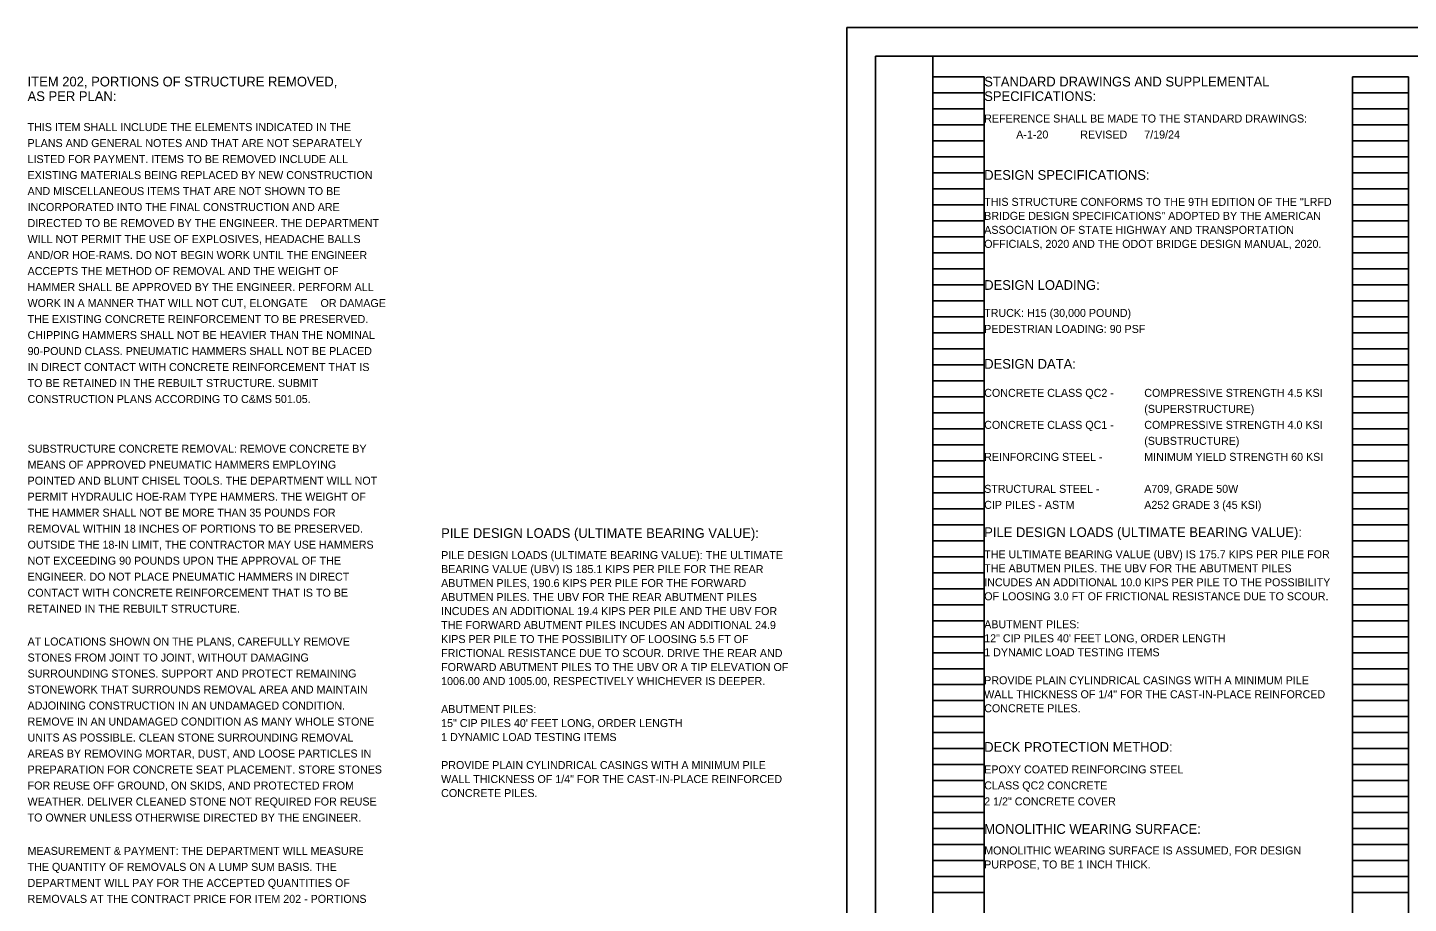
# Model space of a CAD drawing. Extents: x -14.3 to 34, y -8.8 to 27.3.
# Drawn here: x -14.33 to 9.82, y 6.67 to 22 of the extents above; entities that cross this region are included whole.
import ezdxf

# ---------------------------------------------------------------- set-up
doc = ezdxf.new("R2010")
doc.units = 0
for name, color, linetype in [('BR_P_Gen_Text', 7, 'Continuous'), ('SH_Border', 7, 'Continuous'), ('SH_Cut_Line', 7, 'Continuous'), ('SH_Data', 7, 'Continuous')]:
    doc.layers.add(name, color=color, linetype=linetype)

msp = doc.modelspace()

# ---------------------------------------------------------------- linework, layer by layer
at = {"layer": 'SH_Border'}
for points in [[(0.5, 21.5), (1.5, 21.5), (1.5, 0.5), (0.5, 0.5)], [(1.5, 21.5), (33.5, 21.5), (33.5, 0.5), (1.5, 0.5)]]:
    msp.add_lwpolyline(points, close=True, dxfattribs=at)
at = {"layer": 'SH_Cut_Line'}
msp.add_lwpolyline([(0, 0), (34, 0), (34, 22), (0, 22)], close=True, dxfattribs=at)
at = {"layer": 'SH_Data'}
for p, q in [((1.5, 0.98), (1.5, 21.14)), ((1.5, 21.14), (2.4, 21.14)), ((2.4, 0.98), (2.4, 21.14)), ((8.84, 0.98), (8.84, 21.14)), ((8.84, 21.14), (9.82, 21.14)), ((9.82, 0.98), (9.82, 21.14)), ((1.5, 20.86), (2.4, 20.86)), ((8.84, 20.86), (9.82, 20.86)), ((1.5, 20.58), (2.4, 20.58)), ((8.84, 20.58), (9.82, 20.58)), ((1.5, 20.3), (2.4, 20.3)), ((8.84, 20.3), (9.82, 20.3)), ((1.5, 20.02), (2.4, 20.02)), ((8.84, 20.02), (9.82, 20.02)), ((1.5, 19.74), (2.4, 19.74)), ((8.84, 19.74), (9.82, 19.74)), ((1.5, 19.46), (2.4, 19.46)), ((8.84, 19.46), (9.82, 19.46)), ((1.5, 19.18), (2.4, 19.18)), ((8.84, 19.18), (9.82, 19.18)), ((1.5, 18.9), (2.4, 18.9)), ((8.84, 18.9), (9.82, 18.9)), ((1.5, 18.62), (2.4, 18.62)), ((8.84, 18.62), (9.82, 18.62)), ((1.5, 18.34), (2.4, 18.34)), ((8.84, 18.34), (9.82, 18.34)), ((1.5, 18.06), (2.4, 18.06)), ((8.84, 18.06), (9.82, 18.06)), ((1.5, 17.78), (2.4, 17.78)), ((8.84, 17.78), (9.82, 17.78)), ((1.5, 17.5), (2.4, 17.5)), ((8.84, 17.5), (9.82, 17.5)), ((1.5, 17.22), (2.4, 17.22)), ((8.84, 17.22), (9.82, 17.22)), ((1.5, 16.94), (2.4, 16.94)), ((8.84, 16.94), (9.82, 16.94)), ((1.5, 16.66), (2.4, 16.66)), ((8.84, 16.66), (9.82, 16.66)), ((1.5, 16.38), (2.4, 16.38)), ((8.84, 16.38), (9.82, 16.38)), ((1.5, 16.1), (2.4, 16.1)), ((8.84, 16.1), (9.82, 16.1)), ((1.5, 15.82), (2.4, 15.82)), ((8.84, 15.82), (9.82, 15.82)), ((1.5, 15.54), (2.4, 15.54)), ((8.84, 15.54), (9.82, 15.54)), ((1.5, 15.26), (2.4, 15.26)), ((8.84, 15.26), (9.82, 15.26)), ((1.5, 14.98), (2.4, 14.98)), ((8.84, 14.98), (9.82, 14.98)), ((1.5, 14.7), (2.4, 14.7)), ((8.84, 14.7), (9.82, 14.7)), ((1.5, 14.42), (2.4, 14.42)), ((8.84, 14.42), (9.82, 14.42)), ((1.5, 14.14), (2.4, 14.14)), ((8.84, 14.14), (9.82, 14.14)), ((1.5, 13.86), (2.4, 13.86)), ((8.84, 13.86), (9.82, 13.86)), ((1.5, 13.58), (2.4, 13.58)), ((8.84, 13.58), (9.82, 13.58)), ((1.5, 13.3), (2.4, 13.3)), ((8.84, 13.3), (9.82, 13.3)), ((1.5, 13.02), (2.4, 13.02)), ((8.84, 13.02), (9.82, 13.02)), ((1.5, 12.74), (2.4, 12.74)), ((8.84, 12.74), (9.82, 12.74)), ((1.5, 12.46), (2.4, 12.46)), ((8.84, 12.46), (9.82, 12.46)), ((1.5, 12.18), (2.4, 12.18)), ((8.84, 12.18), (9.82, 12.18)), ((1.5, 11.9), (2.4, 11.9)), ((8.84, 11.9), (9.82, 11.9)), ((1.5, 11.62), (2.4, 11.62)), ((8.84, 11.62), (9.82, 11.62)), ((1.5, 11.34), (2.4, 11.34)), ((8.84, 11.34), (9.82, 11.34)), ((1.5, 11.06), (2.4, 11.06)), ((8.84, 11.06), (9.82, 11.06)), ((1.5, 10.78), (2.4, 10.78)), ((8.84, 10.78), (9.82, 10.78)), ((1.5, 10.5), (2.4, 10.5)), ((8.84, 10.5), (9.82, 10.5)), ((1.5, 10.22), (2.4, 10.22)), ((8.84, 10.22), (9.82, 10.22)), ((1.5, 9.94), (2.4, 9.94)), ((8.84, 9.94), (9.82, 9.94)), ((1.5, 9.66), (2.4, 9.66)), ((8.84, 9.66), (9.82, 9.66)), ((1.5, 9.38), (2.4, 9.38)), ((8.84, 9.38), (9.82, 9.38)), ((1.5, 9.1), (2.4, 9.1)), ((8.84, 9.1), (9.82, 9.1)), ((1.5, 8.82), (2.4, 8.82)), ((8.84, 8.82), (9.82, 8.82)), ((1.5, 8.54), (2.4, 8.54)), ((8.84, 8.54), (9.82, 8.54)), ((1.5, 8.26), (2.4, 8.26)), ((8.84, 8.26), (9.82, 8.26)), ((1.5, 7.98), (2.4, 7.98)), ((8.84, 7.98), (9.82, 7.98)), ((1.5, 7.7), (2.4, 7.7)), ((8.84, 7.7), (9.82, 7.7)), ((1.5, 7.42), (2.4, 7.42)), ((8.84, 7.42), (9.82, 7.42)), ((1.5, 7.14), (2.4, 7.14)), ((8.84, 7.14), (9.82, 7.14)), ((1.5, 6.86), (2.4, 6.86)), ((8.84, 6.86), (9.82, 6.86))]:
    msp.add_line(p, q, dxfattribs=at)

# ---------------------------------------------------------------- texts
at = {"layer": 'BR_P_Gen_Text'}
for s, height, p in [('ITEM 202, PORTIONS OF STRUCTURE REMOVED, ', 0.17, (-14.334, 20.97)), ('STANDARD DRAWINGS AND SUPPLEMENTAL ', 0.17, (2.4, 20.97)), ('AS PER PLAN:', 0.17, (-14.334, 20.715)), ('SPECIFICATIONS:', 0.17, (2.4, 20.715)), ('THIS ITEM SHALL INCLUDE THE ELEMENTS INDICATED IN THE ', 0.14, (-14.334, 20.189)), ('REFERENCE SHALL BE MADE TO THE STANDARD DRAWINGS:', 0.14, (2.4, 20.339)), ('PLANS AND GENERAL NOTES AND THAT ARE NOT SEPARATELY ', 0.14, (-14.334, 19.909)), ('A-1-20', 0.14, (2.96, 20.059)), ('REVISED', 0.14, (4.08, 20.059)), ('7/19/24', 0.14, (5.2, 20.059)), ('LISTED FOR PAYMENT. ITEMS TO BE REMOVED INCLUDE ALL ', 0.14, (-14.334, 19.629)), ('EXISTING MATERIALS BEING REPLACED BY NEW CONSTRUCTION ', 0.14, (-14.334, 19.349)), ('DESIGN SPECIFICATIONS:', 0.17, (2.4, 19.336)), ('AND MISCELLANEOUS ITEMS THAT ARE NOT SHOWN TO BE ', 0.14, (-14.334, 19.069)), ('INCORPORATED INTO THE FINAL CONSTRUCTION AND ARE ', 0.14, (-14.334, 18.789)), ('THIS STRUCTURE CONFORMS TO THE 9TH EDITION OF THE "LRFD ', 0.14, (2.4, 18.88)), ('DIRECTED TO BE REMOVED BY THE ENGINEER. THE DEPARTMENT ', 0.14, (-14.334, 18.509)), ('BRIDGE DESIGN SPECIFICATIONS" ADOPTED BY THE AMERICAN ', 0.14, (2.4, 18.635)), ('WILL NOT PERMIT THE USE OF EXPLOSIVES, HEADACHE BALLS ', 0.14, (-14.334, 18.229)), ('ASSOCIATION OF STATE HIGHWAY AND TRANSPORTATION ', 0.14, (2.4, 18.39)), ('OFFICIALS, 2020 AND THE ODOT BRIDGE DESIGN MANUAL, 2020.', 0.14, (2.4, 18.145)), ('AND/OR HOE-RAMS. DO NOT BEGIN WORK UNTIL THE ENGINEER ', 0.14, (-14.334, 17.949)), ('ACCEPTS THE METHOD OF REMOVAL AND THE WEIGHT OF ', 0.14, (-14.334, 17.669)), ('HAMMER SHALL BE APPROVED BY THE ENGINEER. PERFORM ALL ', 0.14, (-14.334, 17.389)), ('DESIGN LOADING:', 0.17, (2.4, 17.41)), ('WORK IN A MANNER THAT WILL NOT CUT, ELONGATE', 0.14, (-14.334, 17.109)), (' OR DAMAGE ', 0.14, (-9.262, 17.109)), ('THE EXISTING CONCRETE REINFORCEMENT TO BE PRESERVED. ', 0.14, (-14.334, 16.829)), ('TRUCK: H15 (30,000 POUND)', 0.14, (2.4, 16.936)), ('CHIPPING HAMMERS SHALL NOT BE HEAVIER THAN THE NOMINAL ', 0.14, (-14.334, 16.549)), ('PEDESTRIAN LOADING: 90 PSF', 0.14, (2.4, 16.656)), ('90-POUND CLASS. PNEUMATIC HAMMERS SHALL NOT BE PLACED ', 0.14, (-14.334, 16.269)), ('DESIGN DATA:', 0.17, (2.4, 16.03)), ('IN DIRECT CONTACT WITH CONCRETE REINFORCEMENT THAT IS ', 0.14, (-14.334, 15.989)), ('TO BE RETAINED IN THE REBUILT STRUCTURE. SUBMIT ', 0.14, (-14.334, 15.709)), ('CONSTRUCTION PLANS ACCORDING TO C&MS 501.05. ', 0.14, (-14.334, 15.429)), ('CONCRETE CLASS QC2 - ', 0.14, (2.4, 15.537)), ('COMPRESSIVE STRENGTH 4.5 KSI ', 0.14, (5.2, 15.537)), ('(SUPERSTRUCTURE)', 0.14, (5.2, 15.257)), ('CONCRETE CLASS QC1 - ', 0.14, (2.4, 14.977)), ('COMPRESSIVE STRENGTH 4.0 KSI ', 0.14, (5.2, 14.977)), ('(SUBSTRUCTURE)', 0.14, (5.2, 14.697)), ('SUBSTRUCTURE CONCRETE REMOVAL: REMOVE CONCRETE BY ', 0.14, (-14.334, 14.56)), ('REINFORCING STEEL - ', 0.14, (2.4, 14.417)), ('MINIMUM YIELD STRENGTH 60 KSI', 0.14, (5.2, 14.417)), ('MEANS OF APPROVED PNEUMATIC HAMMERS EMPLOYING ', 0.14, (-14.334, 14.28)), ('POINTED AND BLUNT CHISEL TOOLS. THE DEPARTMENT WILL NOT ', 0.14, (-14.334, 14)), ('PERMIT HYDRAULIC HOE-RAM TYPE HAMMERS. THE WEIGHT OF ', 0.14, (-14.334, 13.72)), ('STRUCTURAL STEEL - ', 0.14, (2.4, 13.857)), ('A709, GRADE 50W ', 0.14, (5.2, 13.857)), ('THE HAMMER SHALL NOT BE MORE THAN 35 POUNDS FOR ', 0.14, (-14.334, 13.44)), ('CIP PILES - ASTM ', 0.14, (2.4, 13.577)), ('A252 GRADE 3 (45 KSI)', 0.14, (5.2, 13.577)), ('REMOVAL WITHIN 18 INCHES OF PORTIONS TO BE PRESERVED. ', 0.14, (-14.334, 13.16)), ('PILE DESIGN LOADS (ULTIMATE BEARING VALUE):', 0.17, (-7.1, 13.068)), ('PILE DESIGN LOADS (ULTIMATE BEARING VALUE):', 0.17, (2.4, 13.083)), ('OUTSIDE THE 18-IN LIMIT, THE CONTRACTOR MAY USE HAMMERS ', 0.14, (-14.334, 12.88)), ('PILE DESIGN LOADS (ULTIMATE BEARING VALUE): THE ULTIMATE ', 0.14, (-7.1, 12.698)), ('THE ULTIMATE BEARING VALUE (UBV) IS 175.7 KIPS PER PILE FOR ', 0.14, (2.4, 12.712)), ('NOT EXCEEDING 90 POUNDS UPON THE APPROVAL OF THE ', 0.14, (-14.334, 12.6)), ('BEARING VALUE (UBV) IS 185.1 KIPS PER PILE FOR THE REAR ', 0.14, (-7.1, 12.453)), ('THE ABUTMEN PILES. THE UBV FOR THE ABUTMENT PILES ', 0.14, (2.4, 12.467)), ('ENGINEER. DO NOT PLACE PNEUMATIC HAMMERS IN DIRECT ', 0.14, (-14.334, 12.32)), ('ABUTMEN PILES, 190.6 KIPS PER PILE FOR THE FORWARD ', 0.14, (-7.1, 12.208)), ('INCUDES AN ADDITIONAL 10.0 KIPS PER PILE TO THE POSSIBILITY ', 0.14, (2.4, 12.222)), ('CONTACT WITH CONCRETE REINFORCEMENT THAT IS TO BE ', 0.14, (-14.334, 12.04)), ('ABUTMEN PILES. THE UBV FOR THE REAR ABUTMENT PILES ', 0.14, (-7.1, 11.963)), ('OF LOOSING 3.0 FT OF FRICTIONAL RESISTANCE DUE TO SCOUR. ', 0.14, (2.4, 11.977)), ('RETAINED IN THE REBUILT STRUCTURE.', 0.14, (-14.334, 11.76)), ('INCUDES AN ADDITIONAL 19.4 KIPS PER PILE AND THE UBV FOR ', 0.14, (-7.1, 11.718)), ('THE FORWARD ABUTMENT PILES INCUDES AN ADDITIONAL 24.9 ', 0.14, (-7.1, 11.473)), ('ABUTMENT PILES:', 0.14, (2.4, 11.487)), ('KIPS PER PILE TO THE POSSIBILITY OF LOOSING 5.5 FT OF ', 0.14, (-7.1, 11.228)), ('12" CIP PILES 40\' FEET LONG, ORDER LENGTH', 0.14, (2.4, 11.242)), ('AT LOCATIONS SHOWN ON THE PLANS, CAREFULLY REMOVE ', 0.14, (-14.334, 11.185)), ('FRICTIONAL RESISTANCE DUE TO SCOUR. DRIVE THE REAR AND ', 0.14, (-7.1, 10.983)), ('1 DYNAMIC LOAD TESTING ITEMS ', 0.14, (2.4, 10.997)), ('STONES FROM JOINT TO JOINT, WITHOUT DAMAGING ', 0.14, (-14.334, 10.905)), ('FORWARD ABUTMENT PILES TO THE UBV OR A TIP ELEVATION OF ', 0.14, (-7.1, 10.738)), ('SURROUNDING STONES. SUPPORT AND PROTECT REMAINING ', 0.14, (-14.334, 10.625)), ('1006.00 AND 1005.00, RESPECTIVELY WHICHEVER IS DEEPER. ', 0.14, (-7.1, 10.493)), ('PROVIDE PLAIN CYLINDRICAL CASINGS WITH A MINIMUM PILE ', 0.14, (2.4, 10.507)), ('STONEWORK THAT SURROUNDS REMOVAL AREA AND MAINTAIN ', 0.14, (-14.334, 10.345)), ('WALL THICKNESS OF 1/4" FOR THE CAST-IN-PLACE REINFORCED ', 0.14, (2.4, 10.262)), ('ADJOINING CONSTRUCTION IN AN UNDAMAGED CONDITION. ', 0.14, (-14.334, 10.065)), ('ABUTMENT PILES:', 0.14, (-7.1, 10.003)), ('CONCRETE PILES.', 0.14, (2.4, 10.017)), ('REMOVE IN AN UNDAMAGED CONDITION AS MANY WHOLE STONE ', 0.14, (-14.334, 9.785)), ('15" CIP PILES 40\' FEET LONG, ORDER LENGTH', 0.14, (-7.1, 9.758)), ('UNITS AS POSSIBLE. CLEAN STONE SURROUNDING REMOVAL ', 0.14, (-14.334, 9.505)), ('1 DYNAMIC LOAD TESTING ITEMS ', 0.14, (-7.1, 9.513)), ('DECK PROTECTION METHOD:', 0.17, (2.4, 9.325)), ('AREAS BY REMOVING MORTAR, DUST, AND LOOSE PARTICLES IN ', 0.14, (-14.334, 9.225)), ('PREPARATION FOR CONCRETE SEAT PLACEMENT. STORE STONES ', 0.14, (-14.334, 8.945)), ('PROVIDE PLAIN CYLINDRICAL CASINGS WITH A MINIMUM PILE ', 0.14, (-7.1, 9.023)), ('EPOXY COATED REINFORCING STEEL ', 0.14, (2.4, 8.947)), ('FOR REUSE OFF GROUND, ON SKIDS, AND PROTECTED FROM ', 0.14, (-14.334, 8.665)), ('WALL THICKNESS OF 1/4" FOR THE CAST-IN-PLACE REINFORCED ', 0.14, (-7.1, 8.778)), ('CLASS QC2 CONCRETE', 0.14, (2.4, 8.667)), ('WEATHER. DELIVER CLEANED STONE NOT REQUIRED FOR REUSE ', 0.14, (-14.334, 8.385)), ('CONCRETE PILES.', 0.14, (-7.1, 8.533)), ('2 1/2" CONCRETE COVER', 0.14, (2.4, 8.387)), ('TO OWNER UNLESS OTHERWISE DIRECTED BY THE ENGINEER.', 0.14, (-14.334, 8.105)), ('MONOLITHIC WEARING SURFACE:', 0.17, (2.4, 7.889)), ('MEASUREMENT & PAYMENT: THE DEPARTMENT WILL MEASURE ', 0.14, (-14.334, 7.521)), ('MONOLITHIC WEARING SURFACE IS ASSUMED, FOR DESIGN ', 0.14, (2.4, 7.528)), ('THE QUANTITY OF REMOVALS ON A LUMP SUM BASIS. THE ', 0.14, (-14.334, 7.241)), ('PURPOSE, TO BE 1 INCH THICK.', 0.14, (2.4, 7.283)), ('DEPARTMENT WILL PAY FOR THE ACCEPTED QUANTITIES OF ', 0.14, (-14.334, 6.961)), ('REMOVALS AT THE CONTRACT PRICE FOR ITEM 202 - PORTIONS ', 0.14, (-14.334, 6.681))]:
    msp.add_text(s, height=height, dxfattribs=at).set_placement(p)

doc.saveas('drawing.dxf')
